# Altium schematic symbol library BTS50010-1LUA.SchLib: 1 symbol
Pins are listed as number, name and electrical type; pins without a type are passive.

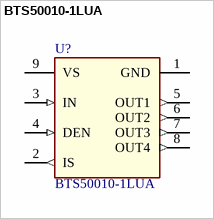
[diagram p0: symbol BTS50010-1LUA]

## BTS50010-1LUA
designator U?
Smart High-Side Power Switch; Manufacturer: Infineon Technologies
pins: 1 GND (power) "Ground", 2 IS (out) "Sense", 3 IN (in) "Input", 4 DEN (in) "Diagnosis enable", 5 OUT1 (out) "Output", 6 OUT2 (out) "Output", 7 OUT3 (out) "Output", 8 OUT4 (out) "Output", 9 VS (power) "Supply Voltage(Cooling tab)"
